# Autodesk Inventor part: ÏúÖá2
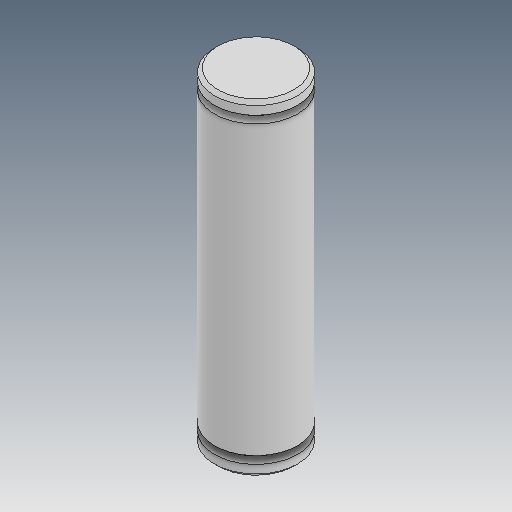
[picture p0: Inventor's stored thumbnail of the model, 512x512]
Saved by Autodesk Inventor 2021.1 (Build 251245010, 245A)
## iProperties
Created: 2014-12
Part Number: ÏúÖá2
Material: Ogólny
Document SubType Name: Modeling
Designer: user
Density: 1 g/cm^3
Appearance: Domyślna
Author: user
Revision Number: ÈÎºÎ
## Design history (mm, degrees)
feature "ÊäÈë1"
node "Bryła1"
